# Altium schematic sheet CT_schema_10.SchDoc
size 226 x 144 mm
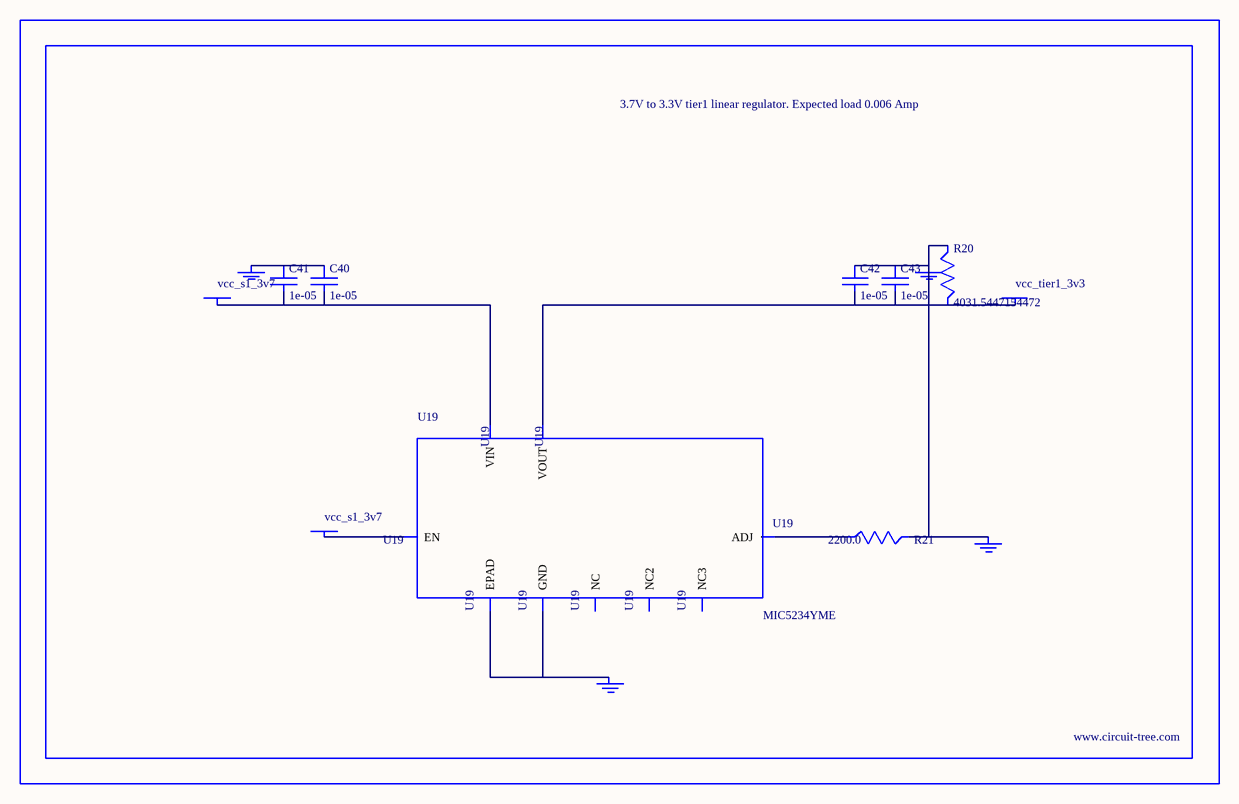
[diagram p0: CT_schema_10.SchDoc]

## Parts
BORDER9  (no value)
C40  1e-05  [C1210]
C41  1e-05  [C1210]
C42  1e-05  [C1210]
C43  1e-05  [C1210]
GND_INSTANCE_9_0  (no value)
GND_INSTANCE_9_1  (no value)
GND_INSTANCE_9_2  (no value)
GND_INSTANCE_9_3  (no value)
POWER_INSTANCE_9_0  vcc_tier1_3v3
POWER_INSTANCE_9_1  vcc_s1_3v7
POWER_INSTANCE_9_2  vcc_s1_3v7
R20  4031.5447154472  [R0603]
R21  2200.0  [R0603]
U19  MIC5234YME  [SOIC-8_EP]

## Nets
NetC40_1: C40.1 C41.1 GND_INSTANCE_9_3.0(GND)
NetC40_2: C40.2 C41.2 POWER_INSTANCE_9_2.0(PWR) U19.8(VIN)
NetC42_1: C42.1 C43.1 GND_INSTANCE_9_0.0(GND) GND_INSTANCE_9_1.0(GND) R20.1 R21.2
NetC42_2: C42.2 C43.2 POWER_INSTANCE_9_0.0(PWR) R20.2 U19.1(VOUT)
NetGND_INSTANCE_9_2_0: GND_INSTANCE_9_2.0(GND) U19.7(GND) U19.EPAD
NetPOWER_INSTANCE_9_1_0: POWER_INSTANCE_9_1.0(PWR) U19.5(EN)
NetR21_1: R21.1 U19.4(ADJ)

Not connected (* = marked no-connect by the designer): U19 2(NC) 3(NC2) 6(NC3)

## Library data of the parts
BORDER9 = BORDER_PAGE9
C40-C43 = C1210C106K5PACTU
GND_INSTANCE_9_0-GND_INSTANCE_9_3 = GND
POWER_INSTANCE_9_0-POWER_INSTANCE_9_2 = PWR
R20 = R20
R21 = RC0603JR-072K2L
